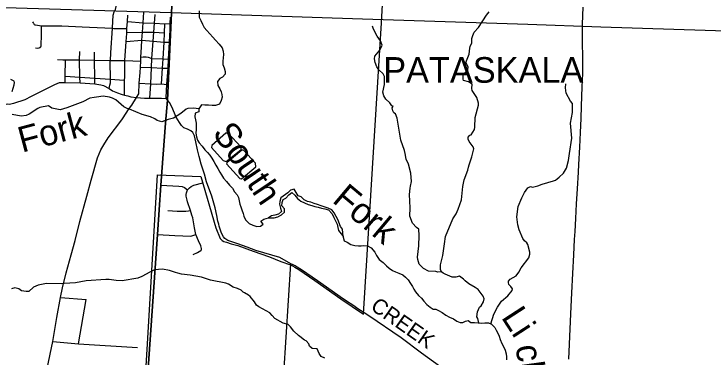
# Model space of a CAD drawing. Extents: x 0 to 34, y 0 to 22.
# Drawn here: x 5.796 to 8.377, y 18.654 to 19.923 of the extents above; entities that cross this region are included whole.
import ezdxf

# ---------------------------------------------------------------- set-up
doc = ezdxf.new("R2010")
doc.units = 0
for name, color, linetype in [('GM_X_City_Street', 7, 'Continuous'), ('GM_X_Corporation', 7, 'Continuous'), ('GM_X_Corporation_Text', 7, 'Continuous'), ('GM_X_County_Road', 7, 'Continuous'), ('GM_X_Major_River', 7, 'Continuous'), ('GM_X_Major_River_Text', 7, 'Continuous'), ('GM_X_Minor_Lake', 7, 'Continuous'), ('GM_X_Minor_River', 7, 'Continuous'), ('GM_X_Minor_River_Text', 7, 'Continuous'), ('GM_X_Rail_Line', 7, 'Continuous'), ('GM_X_State_Route', 7, 'Continuous'), ('GM_X_Township_Road', 7, 'Continuous'), ('GM_X_Township_Road_Text', 7, 'Continuous')]:
    doc.layers.add(name, color=color, linetype=linetype)

msp = doc.modelspace()

# ---------------------------------------------------------------- linework, layer by layer
at = {"layer": 'GM_X_City_Street'}
for p, q in [((6.2148, 19.8942), (6.2723, 19.8903)), ((6.2723, 19.8903), (6.3146, 19.8887)), ((6.2121, 19.8536), (6.2703, 19.8558)), ((6.21, 19.8206), (6.2677, 19.8252)), ((5.9678, 18.8736), (6.0619, 18.8661)), ((6.0334, 18.7031), (6.0619, 18.8661))]:
    msp.add_line(p, q, dxfattribs=at)
for points in [[(6.1621, 19.9187), (6.1651, 19.9305), (6.1671, 19.9331), (6.1677, 19.9339), (6.1707, 19.9396), (6.173, 19.9503), (6.1797, 19.9907), (6.1851, 20.0821), (6.1885, 20.1496), (6.1918, 20.2193)], [(6.2605, 18.224), (6.3251, 19.3282), (6.486, 19.3213), (6.5406, 19.1314), (6.5574, 19.092), (6.5605, 19.0886), (6.5647, 19.0849), (6.5708, 19.0815), (6.581, 19.0781), (6.5981, 19.0725), (6.6221, 19.0665), (6.6787, 19.0451), (6.7388, 19.0245), (6.7814, 19.0075), (6.8171, 18.9948), (6.824, 18.9914), (6.8323, 18.9865), (6.8472, 18.9774), (6.9066, 18.9367), (7.0025, 18.8687), (7.0867, 18.8127), (7.1529, 19.8898), (7.1715, 20.2288)], [(6.1467, 19.6467), (6.1496, 19.6593), (6.152, 19.6677), (6.1519, 19.6813), (6.1513, 19.7468), (6.1516, 19.751), (6.1538, 19.7783), (6.1595, 19.8695), (6.1596, 19.8709), (6.1621, 19.9187)], [(6.213, 19.8684), (6.2148, 19.8942), (6.2162, 19.9185)], [(6.2971, 19.6116), (6.3005, 19.6646), (6.3035, 19.7245), (6.3052, 19.7583), (6.3092, 19.822), (6.3127, 19.8559), (6.3146, 19.8887), (6.3173, 19.9206)], [(6.3561, 19.6097), (6.3582, 19.614), (6.3607, 19.6619), (6.3652, 19.7217), (6.3659, 19.7554), (6.3696, 19.8186), (6.3722, 19.8639), (6.3726, 19.8873), (6.3731, 19.9103)], [(5.8643, 19.8933), (5.8662, 19.8898), (5.8673, 19.888), (5.8692, 19.8861), (5.8707, 19.8838), (5.8726, 19.883), (5.8749, 19.8827), (5.8973, 19.8789), (5.9726, 19.8788), (6.0473, 19.8751), (6.074, 19.8737), (6.1595, 19.8695), (6.1646, 19.8693), (6.213, 19.8684)], [(5.8752, 19.7969), (5.8835, 19.7965), (5.8892, 19.7977), (5.8911, 19.7981), (5.8926, 19.7985), (5.8937, 19.8007), (5.8948, 19.8015), (5.896, 19.8042), (5.8963, 19.8057), (5.8963, 19.8087), (5.897, 19.8429), (5.8973, 19.8789)], [(6.3146, 19.8887), (6.3525, 19.8866), (6.3726, 19.8873)], [(6.3409, 19.6636), (6.3443, 19.7224), (6.3462, 19.7568), (6.3507, 19.8181), (6.3516, 19.8529), (6.3525, 19.8866)], [(6.2044, 19.6218), (6.2051, 19.7442), (6.2055, 19.7503), (6.21, 19.8206), (6.2119, 19.8507), (6.2121, 19.8536), (6.213, 19.8684)], [(6.2703, 19.8558), (6.3127, 19.8559), (6.3516, 19.8529)], [(6.2677, 19.8252), (6.3092, 19.822), (6.3507, 19.8181), (6.3696, 19.8186)], [(6.0398, 19.668), (6.0394, 19.6893), (6.0379, 19.7524), (6.0379, 19.7531), (6.0387, 19.7837)], [(6.0947, 19.6639), (6.0943, 19.6854), (6.093, 19.7517), (6.0925, 19.7812)], [(5.9559, 19.7539), (5.9766, 19.7532), (5.9855, 19.7531), (6.0379, 19.7524), (6.093, 19.7517), (6.1516, 19.751), (6.2055, 19.7503), (6.2638, 19.7483)], [(5.9843, 19.6691), (5.9846, 19.6931), (5.9855, 19.7531)], [(6.2647, 19.7631), (6.2728, 19.7636), (6.2843, 19.7635), (6.2912, 19.7623), (6.3052, 19.7583), (6.3462, 19.7568), (6.3659, 19.7554)], [(6.2628, 19.7259), (6.3035, 19.7245), (6.3443, 19.7224), (6.3652, 19.7217)], [(5.9846, 19.6931), (6.0394, 19.6893), (6.0943, 19.6854), (6.1519, 19.6813), (6.2009, 19.6779)], [(5.8364, 19.6057), (5.8605, 19.619), (5.9462, 19.6615), (5.9641, 19.6687), (5.9843, 19.6691), (6.0398, 19.668), (6.0947, 19.6639), (6.1162, 19.6606), (6.1257, 19.6575), (6.1467, 19.6467), (6.1599, 19.6382), (6.1781, 19.6311), (6.1921, 19.6261), (6.2044, 19.6218), (6.2157, 19.6195), (6.2266, 19.6162), (6.2484, 19.6135)], [(6.2582, 19.6671), (6.3005, 19.6646), (6.3205, 19.6632), (6.3409, 19.6636), (6.3607, 19.6619)], [(5.0958, 19.6447), (5.259, 19.6246), (5.753, 19.5898), (5.7572, 19.5902), (5.7617, 19.5891), (5.7663, 19.5891), (5.7716, 19.5899), (5.7788, 19.5896), (5.7845, 19.5907), (5.7894, 19.5915), (5.7951, 19.5927), (5.8364, 19.6057)], [(6.2484, 19.6135), (6.2771, 19.6114), (6.2971, 19.6116), (6.3399, 19.6116), (6.3561, 19.6097)], [(6.553, 19.1379), (6.5516, 19.1456), (6.549, 19.1568), (6.5452, 19.1777), (6.5389, 19.206), (6.5264, 19.2486), (6.5064, 19.3023), (6.4989, 19.3303), (6.4875, 19.3665), (6.4799, 19.3958), (6.4739, 19.4202), (6.4673, 19.4499), (6.4617, 19.4718), (6.456, 19.4838), (6.4482, 19.4907), (6.4363, 19.496), (6.4234, 19.5016), (6.4141, 19.5102), (6.4067, 19.5218), (6.395, 19.541), (6.3781, 19.5792), (6.3699, 19.5949), (6.3623, 19.6039), (6.3561, 19.6097)], [(5.9396, 18.7109), (6.0334, 18.7031), (6.2513, 18.6892)]]:
    msp.add_lwpolyline(points, dxfattribs=at)
at = {"layer": 'GM_X_Corporation'}
msp.add_lwpolyline([(3.4218, 18.4152), (4.6285, 18.3373), (5.2113, 18.299), (5.2682, 18.2953), (5.912, 18.251), (6.0938, 18.2359), (6.2646, 18.2231), (6.3253, 19.1073), (6.3374, 19.2897), (6.3556, 19.5188), (6.3621, 19.6044), (6.385, 20.0884), (6.3883, 20.1254), (6.389, 20.1539), (6.3927, 20.2003), (6.4001, 20.2844), (6.4016, 20.3608), (6.4097, 20.4361), (6.4277, 20.7531), (6.4325, 20.8009), (6.4385, 20.9), (2.1, 20.9)], dxfattribs=at)
msp.add_lwpolyline([(8.9, 18.0808), (8.9, 20.9), (6.4385, 20.9), (6.4325, 20.8009), (6.4277, 20.7531), (6.4097, 20.4361), (6.4016, 20.3608), (6.4001, 20.2844), (6.3927, 20.2003), (6.389, 20.1539), (6.3883, 20.1254), (6.385, 20.0884), (6.3621, 19.6044), (6.3556, 19.5188), (6.3374, 19.2897), (6.3253, 19.1073), (6.2646, 18.2231), (6.7672, 18.2007), (7.0679, 18.1923), (7.755, 18.1483), (7.8208, 18.1434), (8.8282, 18.0842)], close=True, dxfattribs=at)
at = {"layer": 'GM_X_County_Road'}
msp.add_lwpolyline([(7.8445, 18.6458), (7.847, 18.7012), (7.8519, 18.8137), (7.8559, 18.8909), (7.8596, 18.963), (7.8635, 19.0321), (7.8661, 19.0882), (7.868, 19.1185), (7.8707, 19.1665), (7.8731, 19.2209), (7.8762, 19.2763), (7.88, 19.338), (7.8817, 19.3661), (7.8853, 19.4295), (7.8881, 19.4839), (7.8903, 19.5361), (7.8921, 19.5815), (7.8945, 19.6532), (7.8961, 19.7025), (7.8959, 19.7327), (7.896, 19.7749), (7.8952, 19.8049), (7.8948, 19.8459), (7.895, 19.864), (7.8949, 19.8769), (7.8952, 19.8844), (7.8977, 19.9474)], dxfattribs=at)
at = {"layer": 'GM_X_Major_River'}
for points in [[(6.4792, 19.934), (6.4791, 19.9211), (6.4797, 19.9113), (6.4853, 19.8983), (6.4913, 19.885), (6.498, 19.8728), (6.5077, 19.861), (6.5186, 19.8491), (6.5299, 19.8373), (6.5404, 19.8251), (6.5528, 19.8113), (6.5644, 19.7979), (6.5685, 19.7854), (6.5688, 19.7729), (6.5683, 19.7607), (6.5671, 19.7482), (6.5666, 19.7357), (6.5714, 19.7228), (6.5751, 19.7095), (6.5754, 19.7), (6.5659, 19.6883), (6.556, 19.6834), (6.5468, 19.6733), (6.5486, 19.6585), (6.5553, 19.6463), (6.5609, 19.6345), (6.5638, 19.6246), (6.5642, 19.6151), (6.5614, 19.6022), (6.5541, 19.589), (6.5404, 19.5842), (6.5276, 19.5843), (6.5139, 19.5855), (6.5003, 19.5852), (6.4878, 19.5861), (6.4782, 19.5721), (6.4778, 19.5604), (6.4652, 19.5551), (6.4632, 19.5426), (6.4658, 19.5305), (6.468, 19.5191), (6.469, 19.5084), (6.4685, 19.4955), (6.4677, 19.4815), (6.4695, 19.4682), (6.4732, 19.4561), (6.4799, 19.4461), (6.4904, 19.4332), (6.5005, 19.4206), (6.5099, 19.4102), (6.5185, 19.3999), (6.526, 19.3893), (6.5331, 19.3774), (6.541, 19.3637), (6.5481, 19.3508), (6.5563, 19.3374), (6.5615, 19.3279), (6.5698, 19.3153), (6.5799, 19.3027), (6.5912, 19.2894), (6.6024, 19.2783), (6.6103, 19.2646), (6.6197, 19.2531), (6.6245, 19.2432), (6.6274, 19.2314), (6.63, 19.2189), (6.6333, 19.209), (6.637, 19.1976), (6.6418, 19.1846), (6.6448, 19.1744), (6.6508, 19.161), (6.6647, 19.148), (6.6782, 19.1419), (6.6922, 19.1368)], [(7.0108, 19.0994), (7.0087, 19.1261), (7.0016, 19.136), (6.992, 19.1619), (6.9852, 19.174), (6.9778, 19.1874), (6.9695, 19.1988), (6.9556, 19.2042), (6.9416, 19.2089), (6.9295, 19.2132), (6.9167, 19.2178), (6.9046, 19.2213), (6.8925, 19.226), (6.88, 19.2295), (6.8668, 19.2357), (6.8567, 19.246), (6.8457, 19.2495), (6.8375, 19.2617), (6.8304, 19.2743), (6.8171, 19.2709), (6.8072, 19.2612), (6.7813, 19.2424), (6.7778, 19.2291), (6.7765, 19.2189), (6.7802, 19.2045), (6.7839, 19.1923), (6.7725, 19.1817), (6.7596, 19.1781), (6.7467, 19.1755), (6.736, 19.1691)], [(6.736, 19.1691), (6.7443, 19.1687), (6.7565, 19.169), (6.7698, 19.1727), (6.7831, 19.1794), (6.7941, 19.1899), (6.7946, 19.2021), (6.7848, 19.2131), (6.7861, 19.2249), (6.7903, 19.2366), (6.7998, 19.2415), (6.8109, 19.2532), (6.8223, 19.2622), (6.8325, 19.2522), (6.8422, 19.2396), (6.855, 19.2297), (6.869, 19.2239), (6.8818, 19.2181), (6.8958, 19.2138), (6.9064, 19.2111), (6.9192, 19.2076), (6.9313, 19.2041), (6.9442, 19.2024), (6.957, 19.1982), (6.9702, 19.184), (6.9773, 19.1703), (6.9836, 19.1577), (6.9896, 19.1452), (6.9921, 19.1326), (6.9947, 19.1212), (7.0037, 19.1094), (7.0108, 19.0994)], [(6.6922, 19.1368), (6.7055, 19.1375), (6.7165, 19.1446), (6.7071, 19.1557), (6.7178, 19.1632), (6.736, 19.1691)], [(7.0108, 19.0994), (7.0113, 19.0975), (7.0156, 19.0835), (7.0258, 19.0781), (7.0397, 19.0704), (7.0548, 19.0658), (7.0677, 19.0645), (7.0779, 19.0656), (7.0874, 19.0663), (7.101, 19.065), (7.115, 19.0577), (7.1281, 19.0417), (7.1348, 19.0287), (7.1438, 19.0146), (7.1585, 19.0028), (7.1713, 18.9905), (7.1814, 18.9825), (7.1935, 18.9744), (7.2048, 18.9683), (7.2173, 18.9644), (7.2312, 18.9578), (7.2414, 18.949), (7.2515, 18.9391), (7.2601, 18.9257), (7.2673, 18.9147), (7.2725, 18.9048), (7.2781, 18.8949), (7.2893, 18.8819), (7.3006, 18.8712), (7.3096, 18.8605), (7.3209, 18.8482), (7.3329, 18.8387), (7.3435, 18.8314), (7.3533, 18.8302), (7.3635, 18.8255), (7.3767, 18.8186), (7.3899, 18.8083), (7.4038, 18.8013), (7.4182, 18.7948), (7.4317, 18.7859), (7.4438, 18.7817), (7.4537, 18.7816), (7.4632, 18.7865), (7.4731, 18.7894), (7.4828, 18.7821), (7.4965, 18.7809), (7.5093, 18.78), (7.5211, 18.7796), (7.5347, 18.7802), (7.5476, 18.7801), (7.5597, 18.7751), (7.5709, 18.7636), (7.5758, 18.7537), (7.581, 18.7442), (7.587, 18.7309), (7.591, 18.7187), (7.597, 18.7042), (7.603, 18.6928), (7.6093, 18.6795), (7.6133, 18.665), (7.6144, 18.6548), (7.6143, 18.6434)]]:
    msp.add_lwpolyline(points, dxfattribs=at)
at = {"layer": 'GM_X_Minor_Lake'}
for points in [[(6.578, 19.4818), (6.5264, 19.4356), (6.5256, 19.4284), (6.5687, 19.3805), (6.5793, 19.3767)], [(6.5793, 19.3767), (6.6346, 19.4217), (6.635, 19.4301), (6.5867, 19.4814), (6.578, 19.4818)], [(6.6879, 19.3704), (6.6437, 19.4191), (6.6369, 19.4187), (6.5827, 19.3733), (6.5811, 19.3683)], [(6.5811, 19.3683), (6.6299, 19.314), (6.6356, 19.3124), (6.689, 19.3575), (6.6879, 19.3704)]]:
    msp.add_lwpolyline(points, dxfattribs=at)
at = {"layer": 'GM_X_Minor_River'}
for points in [[(7.5127, 18.7799), (7.5085, 18.7962), (7.5047, 18.8026), (7.507, 18.8205), (7.5154, 18.8387), (7.5215, 18.8432), (7.5291, 18.8576), (7.5321, 18.869), (7.5284, 18.8785), (7.5102, 18.9036), (7.4989, 18.9108), (7.4754, 18.9249), (7.4618, 18.9356), (7.4562, 18.942), (7.4407, 18.9527), (7.427, 18.9489), (7.4145, 18.9497), (7.3884, 18.9604), (7.3812, 18.9638), (7.3756, 18.968), (7.3703, 18.976), (7.3714, 18.9946), (7.3795, 19.0287), (7.3852, 19.072), (7.3895, 19.0997), (7.4169, 19.1653), (7.429, 19.1839), (7.4359, 19.2006), (7.4484, 19.2354), (7.4534, 19.2844), (7.4588, 19.3087), (7.4714, 19.3443), (7.4737, 19.3557), (7.4771, 19.3648), (7.487, 19.3944), (7.4935, 19.4232), (7.4916, 19.4316), (7.4769, 19.451), (7.4727, 19.459), (7.4728, 19.4673), (7.4788, 19.4741), (7.4845, 19.476), (7.4963, 19.4953), (7.4982, 19.5037), (7.4986, 19.5394), (7.5109, 19.5856), (7.5112, 19.5921), (7.5056, 19.6141), (7.4882, 19.6396), (7.4871, 19.6464), (7.4879, 19.6635), (7.4747, 19.6719), (7.4554, 19.6761), (7.4539, 19.6818), (7.455, 19.7), (7.4634, 19.7068), (7.4717, 19.7163), (7.4733, 19.7265), (7.4642, 19.7425), (7.4764, 19.7736), (7.4787, 19.7964), (7.4799, 19.8017), (7.4867, 19.8157), (7.4871, 19.8313), (7.4898, 19.8427), (7.4955, 19.8555), (7.5114, 19.8726), (7.5411, 19.9184), (7.5509, 19.9302)], [(7.3747, 18.9692), (7.3615, 18.9681), (7.3536, 18.97), (7.3267, 18.9719), (7.3086, 18.9807), (7.2923, 18.9974), (7.2867, 19.0142), (7.2859, 19.0233), (7.2909, 19.0646), (7.2925, 19.1037), (7.291, 19.1261), (7.282, 19.1333), (7.2676, 19.1489), (7.2578, 19.1744), (7.2583, 19.2055), (7.2561, 19.2549), (7.2592, 19.2784), (7.2603, 19.2856), (7.2634, 19.3034), (7.2608, 19.3338), (7.2525, 19.3668), (7.2439, 19.3855), (7.2401, 19.4063), (7.2375, 19.4181), (7.2243, 19.4553), (7.2105, 19.5374), (7.2041, 19.5529), (7.1988, 19.5564), (7.1946, 19.5647), (7.1927, 19.575), (7.1958, 19.5818), (7.1909, 19.5829), (7.1837, 19.594), (7.1686, 19.6073), (7.1614, 19.6202), (7.1576, 19.6331), (7.1634, 19.6612), (7.1645, 19.6669), (7.1634, 19.6916), (7.1589, 19.7007), (7.1434, 19.7159), (7.1359, 19.7269), (7.1291, 19.7425), (7.1268, 19.7562), (7.1284, 19.766), (7.1345, 19.774), (7.1462, 19.7884), (7.1557, 19.8073), (7.1497, 19.8237), (7.1369, 19.8404), (7.1233, 19.8659), (7.1191, 19.8773)], [(5.7891, 19.6354), (5.796, 19.6601), (5.7975, 19.6692), (5.796, 19.6741), (5.7835, 19.6799)], [(7.5572, 18.7761), (7.5676, 18.812), (7.5809, 18.8381), (7.5961, 18.8601), (7.6192, 18.8806), (7.6356, 18.8999), (7.6367, 18.906), (7.6307, 18.9147), (7.6231, 18.9223), (7.6216, 18.9291), (7.622, 18.9348), (7.6285, 18.9416), (7.6497, 18.9541), (7.6607, 18.9678), (7.6691, 18.9833), (7.6968, 19.0201), (7.7002, 19.0337), (7.7006, 19.0421), (7.6935, 19.0698), (7.6897, 19.0763), (7.6814, 19.0839), (7.6753, 19.0922), (7.661, 19.1241), (7.6569, 19.1431), (7.6532, 19.1727), (7.6578, 19.2103), (7.6707, 19.2425), (7.681, 19.2626), (7.6935, 19.2801), (7.7026, 19.2846), (7.7109, 19.2819), (7.7303, 19.2864), (7.7458, 19.2932), (7.7879, 19.3049), (7.7954, 19.3083), (7.8015, 19.3132), (7.8087, 19.3189), (7.825, 19.3344), (7.836, 19.3519), (7.8441, 19.3811), (7.8475, 19.4065), (7.856, 19.4638), (7.8512, 19.5192), (7.858, 19.5583), (7.8588, 19.5739), (7.8585, 19.5803), (7.8577, 19.5909), (7.8513, 19.5997), (7.8355, 19.6301), (7.8325, 19.6494), (7.8337, 19.6646)], [(6.4782, 19.5721), (6.4581, 19.5743), (6.4373, 19.5729), (6.432, 19.571), (6.4115, 19.5547), (6.3842, 19.5377), (6.3645, 19.5317), (6.3414, 19.5237), (6.324, 19.5287), (6.316, 19.5352), (6.2998, 19.5421), (6.2691, 19.5505), (6.2226, 19.5699), (6.2131, 19.5726), (6.2018, 19.5787), (6.1719, 19.605), (6.1598, 19.6118), (6.1481, 19.6153), (6.1246, 19.618), (6.1003, 19.6146), (6.092, 19.6139), (6.0753, 19.6113), (6.0496, 19.598), (5.9904, 19.575), (5.9662, 19.5679), (5.9359, 19.574), (5.9231, 19.5828), (5.8916, 19.5764), (5.8837, 19.5726), (5.8518, 19.5518), (5.8401, 19.5473), (5.8226, 19.545), (5.7893, 19.5504)], [(6.944, 18.649), (6.93, 18.6563), (6.9228, 18.6669), (6.9156, 18.6844), (6.8971, 18.6852), (6.8873, 18.6936), (6.885, 18.7027), (6.8744, 18.7133), (6.8684, 18.7156), (6.8514, 18.7297), (6.8464, 18.7339), (6.8294, 18.7499), (6.817, 18.7658), (6.8079, 18.7738), (6.7901, 18.7796), (6.7587, 18.7959), (6.7489, 18.8077), (6.741, 18.8172), (6.6997, 18.8397), (6.6914, 18.8458), (6.6842, 18.8584), (6.6684, 18.8774), (6.6612, 18.8831), (6.6464, 18.8911), (6.6415, 18.8934), (6.6351, 18.901), (6.6215, 18.9071), (6.6052, 18.9121), (6.5878, 18.9235), (6.5784, 18.9273), (6.5208, 18.9377), (6.4887, 18.9488), (6.4466, 18.9568), (6.4148, 18.9603), (6.4005, 18.9641), (6.3925, 18.9668), (6.3702, 18.9741), (6.3437, 18.9783), (6.3149, 18.9757), (6.2971, 18.9682), (6.2675, 18.9515), (6.2535, 18.9455), (6.1952, 18.9358), (6.1728, 18.9366), (6.1471, 18.9408), (6.1349, 18.9401), (6.0619, 18.9353), (6.0232, 18.9282), (5.9808, 18.9252), (5.971, 18.9249), (5.9153, 18.9254), (5.885, 18.9198), (5.8683, 18.9126), (5.8501, 18.8967), (5.8403, 18.8956), (5.8232, 18.8983), (5.8138, 18.9066), (5.7982, 18.9097), (5.7865, 18.9063)]]:
    msp.add_lwpolyline(points, dxfattribs=at)
at = {"layer": 'GM_X_Rail_Line'}
msp.add_lwpolyline([(2.1, 20.0629), (2.3112, 20.0558), (2.9425, 20.0365), (3.7259, 20.0086), (4.1377, 19.997), (4.5514, 19.9851), (5.3933, 19.9589), (5.7629, 19.946), (6.3762, 19.9275), (7.0828, 19.9047), (7.6933, 19.8843), (7.9626, 19.8754), (8.7713, 19.8495), (8.9, 19.8461)], dxfattribs=at)
at = {"layer": 'GM_X_State_Route'}
for points in [[(6.2665, 19.8004), (6.2677, 19.8252), (6.2703, 19.8558), (6.2723, 19.8903), (6.2749, 19.9291), (6.2752, 19.9322)], [(6.2612, 19.7063), (6.2628, 19.7259), (6.2638, 19.7483), (6.2647, 19.7631), (6.2665, 19.8004)], [(6.2306, 19.5856), (6.2484, 19.6135), (6.2569, 19.6266), (6.2582, 19.6671), (6.2612, 19.7063)], [(6.2164, 19.565), (6.2292, 19.5835), (6.2306, 19.5856)], [(5.8968, 18.512), (5.9396, 18.7109), (5.9544, 18.8006), (5.9678, 18.8736), (5.9747, 18.9092), (5.9885, 18.9657), (6.0063, 19.0318), (6.0214, 19.0851), (6.0391, 19.1553), (6.0642, 19.2482), (6.0813, 19.3083), (6.1043, 19.3909), (6.1168, 19.4206), (6.1273, 19.4388), (6.1438, 19.4639), (6.1934, 19.5309), (6.2121, 19.5589), (6.2164, 19.565)]]:
    msp.add_lwpolyline(points, dxfattribs=at)
at = {"layer": 'GM_X_Township_Road'}
msp.add_line((6.7674, 18.2001), (6.8177, 18.998), dxfattribs=at)
for points in [[(6.3376, 19.2892), (6.3597, 19.2876), (6.4043, 19.2852), (6.4173, 19.2841), (6.4251, 19.2812), (6.4368, 19.2726)], [(6.4573, 19.0333), (6.474, 19.0401), (6.4856, 19.0477), (6.4877, 19.0505), (6.4882, 19.0553), (6.4861, 19.0647), (6.4773, 19.0835), (6.4676, 19.1065), (6.4617, 19.1322), (6.4586, 19.1532), (6.4557, 19.1686), (6.4527, 19.1789), (6.447, 19.1962), (6.4365, 19.228), (6.4353, 19.2336), (6.4319, 19.2493), (6.4317, 19.2551), (6.4331, 19.2613), (6.4368, 19.2726), (6.4437, 19.2801), (6.4499, 19.2843), (6.4598, 19.2894), (6.4926, 19.2986)], [(6.3637, 19.1955), (6.3988, 19.1933), (6.4308, 19.1931), (6.4404, 19.1949), (6.447, 19.1962)], [(7.0586, 18.8373), (7.0578, 18.8379), (7.0122, 18.8682), (6.9163, 18.9361), (6.8569, 18.9769), (6.842, 18.986), (6.8336, 18.9909), (6.8268, 18.9942), (6.8177, 18.998), (6.7773, 19.0216), (6.6886, 19.0484), (6.6574, 19.0601), (6.6226, 19.0722), (6.6, 19.0797), (6.5856, 19.0843), (6.5749, 19.0917), (6.5689, 19.0989), (6.5619, 19.1113), (6.553, 19.1379)], [(6.3255, 19.1068), (6.3899, 19.1027), (6.4491, 19.1007), (6.4562, 19.1027), (6.4676, 19.1065)], [(7.3888, 18.6035), (7.3008, 18.6681), (7.225, 18.7244), (7.1059, 18.8059), (7.0586, 18.8373)]]:
    msp.add_lwpolyline(points, dxfattribs=at)

# ---------------------------------------------------------------- texts
at = {"layer": 'GM_X_Corporation_Text'}
msp.add_text('PATASKALA', height=0.0947, rotation=0, dxfattribs=at).set_placement((7.1593, 19.6682))
at = {"layer": 'GM_X_Major_River_Text'}
for s, rotation, p in [('South', 304.001, (6.5262, 19.4824)), ('Fork', 320.0013, (6.9673, 19.2292)), ('Li', 303.0013, (7.5929, 18.801)), ('ck', 278.0005, (7.6477, 18.6941))]:
    msp.add_text(s, height=0.09469, rotation=rotation, dxfattribs=at).set_placement(p)
at = {"layer": 'GM_X_Minor_River_Text'}
msp.add_text('Fork', height=0.09469, rotation=14.9988, dxfattribs=at).set_placement((5.8252, 19.4093))
at = {"layer": 'GM_X_Township_Road_Text'}
msp.add_text('CREEK', height=0.05682, rotation=324.9723, dxfattribs=at).set_placement((7.1087, 18.832))

doc.saveas('drawing.dxf')
